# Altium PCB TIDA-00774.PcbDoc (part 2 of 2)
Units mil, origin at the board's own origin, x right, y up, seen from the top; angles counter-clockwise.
Board outline 2559.06 x 2362.2 mil, 4 copper layers (Top Layer, GND, PWR, Bottom Layer), stack 79.834 mil thick; 133 components, 91 nets, 569 pads, 616 vias.
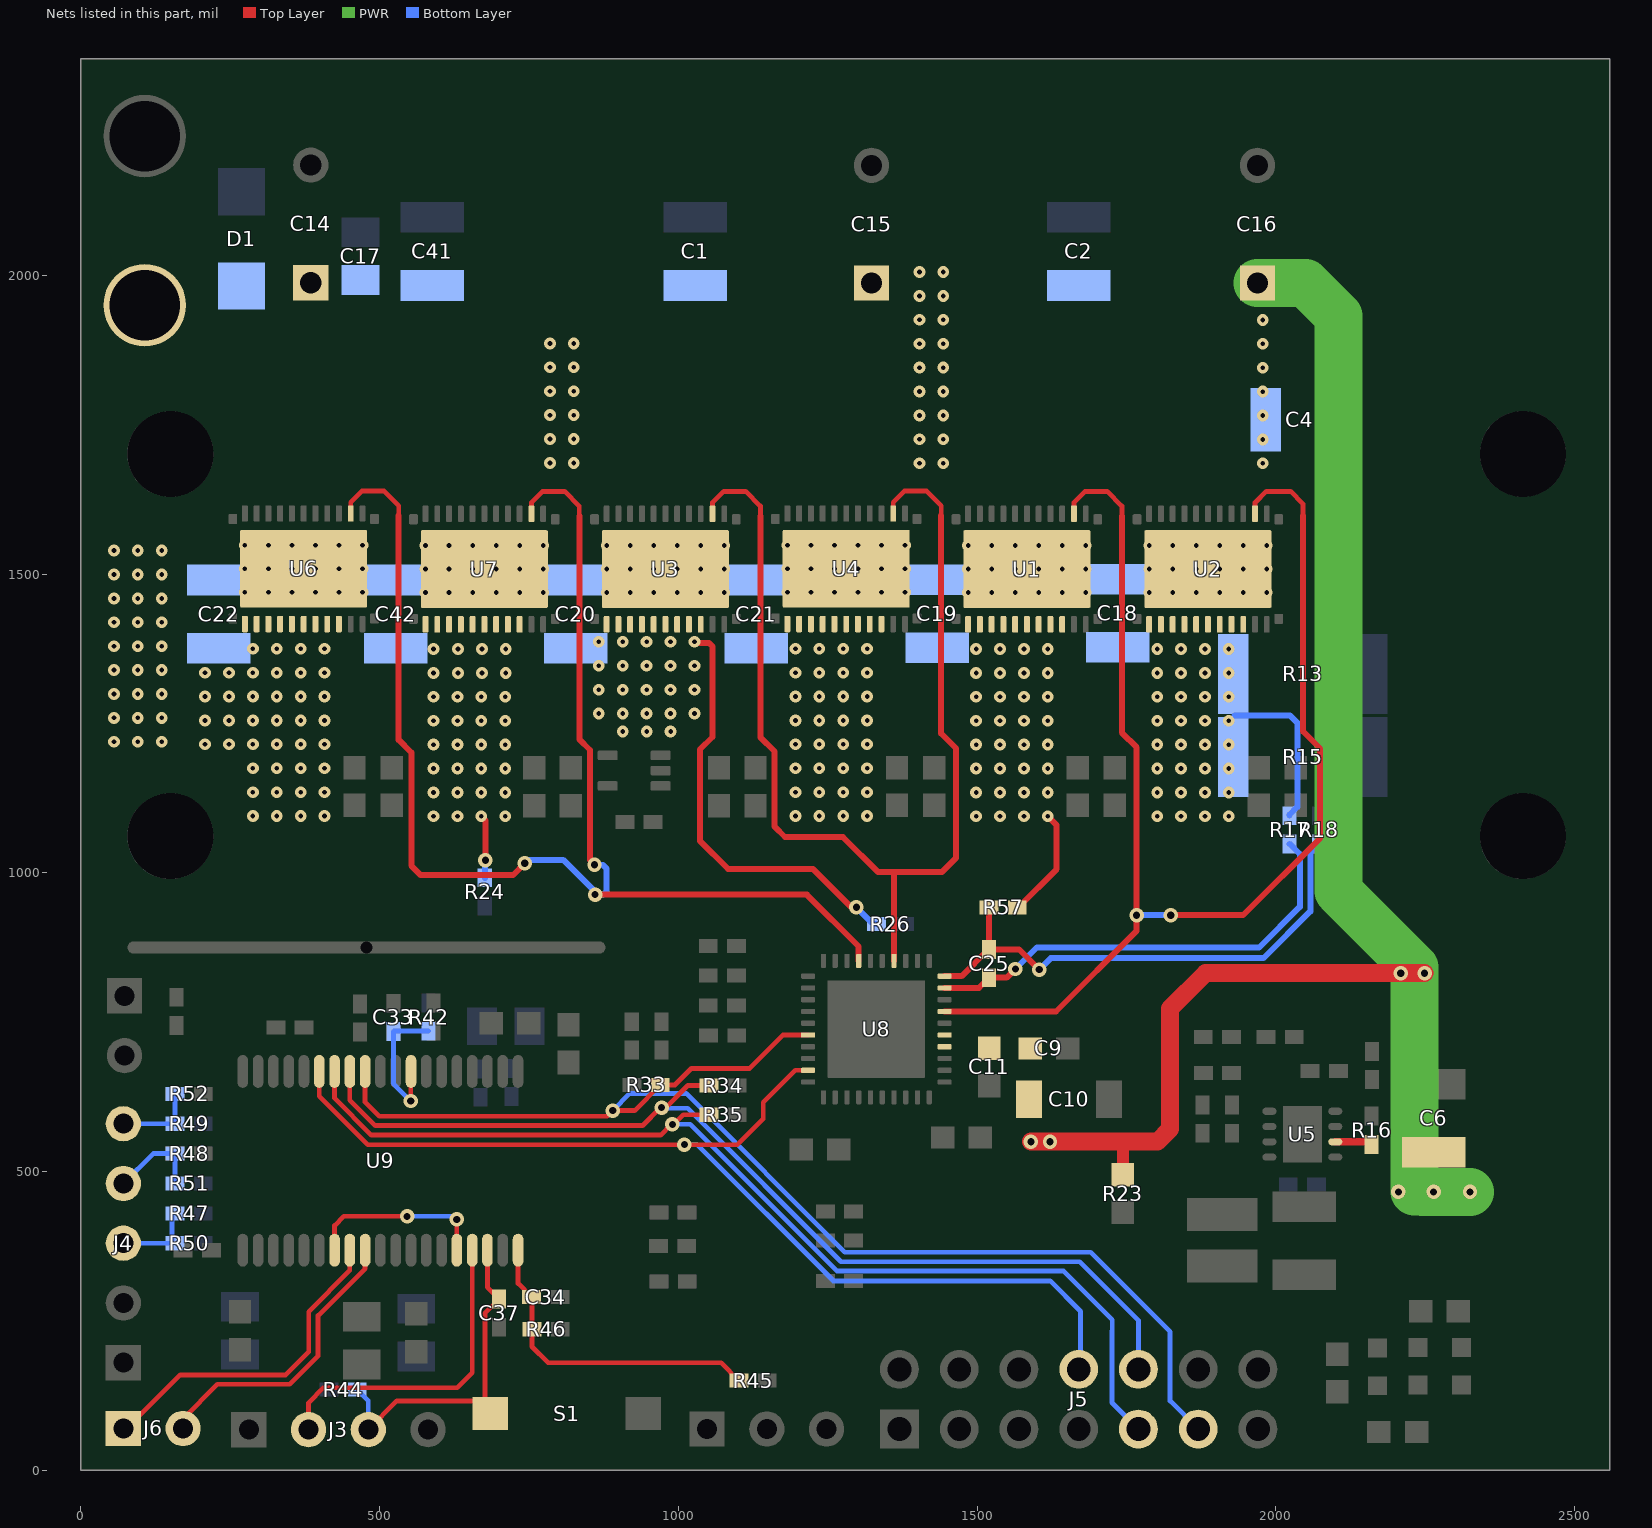
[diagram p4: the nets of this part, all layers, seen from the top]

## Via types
v1: diameter 19.68, hole 7.87, Top Layer to Bottom Layer, 491 vias
v2: diameter 24, hole 12, Top Layer to Bottom Layer, tented both sides, 125 vias

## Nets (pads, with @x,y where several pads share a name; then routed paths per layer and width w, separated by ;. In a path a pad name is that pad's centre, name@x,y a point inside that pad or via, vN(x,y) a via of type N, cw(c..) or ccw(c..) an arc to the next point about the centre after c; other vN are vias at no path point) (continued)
OC_FLT: U9.26 U9.34 | length 305.8
  Top Layer w8: U9.26@424.53,368.39 424.53,409.53 440,425 v2(546,425) ; v2(629,420) 629,368.65 U9.34@629.25,368.39
  Bottom Layer w8: v2(546,425) 624,425 v2(629,420)
PVDD: C1.1 C2.1 C4.1 C6.1 C9.1 C10.2 C11.1 C14.1 C15.1 C16.1 C17.1 C18.1 C19.1 C20.1 C21.1 C22.1 C41.1 C42.1 D1.2 pad.0 R16.2 R23.2 U1.27 U2.27 U3.27 U4.27 U5.2 U6.27 U7.27 U8.4 U8.5 | length 2771.1
  Top Layer w12: U5.2@2099.46,549.73 R16.2@2155.17,549.73
  Top Layer w15: R16.2@2155.17,549.73 R16.2@2161,543.91
  Top Layer w20: R23.2@1744,494.5 1744,549
  Top Layer w30: v2(1590,550) v2(1622,550) 1745,550 ; 1744,549 1745,550 ; v2(2249,832) v2(2209,832) 1882,832 1823,773 1823,571 1802,550 1745,550
  PWR w80: C16.1@1969.23,1987.18 2049.82,1987.18 2105,1932 2105,969 2232.17,841.83 2232.17,466.17 ; 2245,466 v2(2264,466) v2(2325,466)
  other v1: 55.3,1219.26 95.3,1219.26 135.3,1219.26 55.3,1259.26 95.3,1259.26 135.3,1259.26 55.3,1299.26 95.3,1299.26 135.3,1299.26 55.3,1339.26 95.3,1339.26 135.3,1339.26 55.3,1379.26 95.3,1379.26 135.3,1379.26 55.3,1419.26 95.3,1419.26 135.3,1419.26 55.3,1459.26 95.3,1459.26 135.3,1459.26 576.85,1469 616.22,1469 655.59,1469 694.96,1469 734.33,1469 773.7,1469 879.91,1469 919.28,1469 958.65,1469 998.02,1469 1037.39,1469 1076.76,1469 1484.91,1469 1524.28,1469 1563.65,1469 1603.02,1469 1642.39,1469 1681.76,1469 1787.91,1469 1827.28,1469 1866.65,1469 1906.02,1469 1945.39,1469 1984.76,1469 274.46,1469.48 313.83,1469.48 353.2,1469.48 392.57,1469.48 431.94,1469.48 471.31,1469.48 1182.46,1469.48 1221.83,1469.48 1261.2,1469.48 1300.57,1469.48 1339.94,1469.48 1379.31,1469.48 55.3,1499.26 95.3,1499.26 135.3,1499.26 274.46,1508.85 313.83,1508.85 353.2,1508.85 392.57,1508.85 431.94,1508.85 471.31,1508.85 576.85,1508.37 616.22,1508.37 655.59,1508.37 694.96,1508.37 734.33,1508.37 773.7,1508.37 879.91,1508.37 919.28,1508.37 958.65,1508.37 998.02,1508.37 1037.39,1508.37 1076.76,1508.37 1182.46,1508.85 1221.83,1508.85 1261.2,1508.85 1300.57,1508.85 1339.94,1508.85 1379.31,1508.85 1484.91,1508.37 1524.28,1508.37 1563.65,1508.37 1603.02,1508.37 1642.39,1508.37 1681.76,1508.37 1787.91,1508.37 1827.28,1508.37 1866.65,1508.37 1906.02,1508.37 1945.39,1508.37 1984.76,1508.37 55.3,1539.26 95.3,1539.26 135.3,1539.26 274.46,1548.22 313.83,1548.22 353.2,1548.22 392.57,1548.22 431.94,1548.22 471.31,1548.22 576.85,1547.74 616.22,1547.74 655.59,1547.74 694.96,1547.74 734.33,1547.74 773.7,1547.74 879.91,1547.74 919.28,1547.74 958.65,1547.74 998.02,1547.74 1037.39,1547.74 1076.76,1547.74 1182.46,1548.22 1221.83,1548.22 1261.2,1548.22 1300.57,1548.22 1339.94,1548.22 1379.31,1548.22 1484.91,1547.74 1524.28,1547.74 1563.65,1547.74 1603.02,1547.74 1642.39,1547.74 1681.76,1547.74 1787.91,1547.74 1827.28,1547.74 1866.65,1547.74 1906.02,1547.74 1945.39,1547.74 1984.76,1547.74 1978.23,1685.34 785,1686 825,1686 1403.45,1685.52 1443.45,1685.52 1978.23,1725.34 785,1726 825,1726 1403.45,1725.52 1443.45,1725.52 1978.23,1765.34 785,1766 825,1766 1403.45,1765.52 1443.45,1765.52 1978.23,1805.34 785,1806 825,1806 1403.45,1805.52 1443.45,1805.52 1978.23,1845.34 785,1846 825,1846 1403.45,1845.52 1443.45,1845.52 1978.23,1885.34 785,1886 825,1886 1403.45,1885.52 1443.45,1885.52 1978.23,1925.34 1403.45,1925.52 1443.45,1925.52 1403.45,1965.52 1443.45,1965.52 1403.45,2005.52 1443.45,2005.52
  other v2: 2205,466
RST: C37.1 J3.3 R44.1 S1.2 U9.36 | length 589.8
  Top Layer w8: J3.3@481,68 529,116 664.05,116 S1.2@676.21,103.84 ; U9.36@680.43,368.39 680.43,306.19 C37.1@700,286.62 676.21,262.83 S1.2@676.21,103.84 ; S1.2@685.05,95 S1.2@676.21,103.84
  Bottom Layer w8: R44.1@462.62,135 481,116.63 J3.3@481,68
SA: J4.5 R49.1 R52.2 | length 136.4
  Bottom Layer w8: J4.5@71,580 R49.1@157.38,580 R52.2@157.38,630
SB: J4.4 R48.1 R51.2 | length 157.1
  Bottom Layer w8: J4.4@71,480 121,530 R48.1@157.38,530 R51.2@157.38,480
SC: J4.3 R47.1 R50.2 | length 131.4
  Bottom Layer w8: J4.3@71,380 152.38,380 R47.1@152.38,430
SCLK: J5.9 R35.2 U9.13 | length 1793.1
  Top Layer w8: U9.13@424.53,667.61 424.53,622.78 486.19,561.12 970.12,561.12 988,579 v2(990,579) 990,576.8 1008.2,595 R35.2@1051.38,595
  Bottom Layer w8: v2@990,573.18 v2(990,579) 1019.93,579 1265.59,333.34 1278.68,333.34 ; 1278.74,333.4 1644.6,333.4 1726,252 1726,234 1725.72,233.72 1725.72,113.28 J5.9@1770,69
SCS: J5.8 U8.29 U9.14 | length 1838.5
  Top Layer w8: U9.14@398.94,667.61 398.94,626.03 480.17,544.8 480.37,545 v2(1010,545) 1098.6,545 1098.8,544.8 1142,588 1142,616.03 1195.46,669.5 U8.29@1217.16,669.5
  Bottom Layer w8: v2(1010,545) 1031.59,545 1259.59,317 1622,317 1673,266 1673,172 J5.8@1670,169
SDI: J5.10 R34.2 U9.12 | length 1736
  Top Layer w8: U9.12@450.12,667.61 450.12,619.54 492.74,576.92 939.92,576.92 970,607 v2(972,607) 972,602.13 973,601.13 1015.87,644 R34.2@1051.38,644
  Bottom Layer w8: v2(972,607) 970,607 969,606 1015.27,606 1272.14,349.14 1272.2,349.2 1671.8,349.2 1770,251 J5.10@1770,169
SDO: J5.11 R33.2 U8.26 U9.11 | length 2151.4
  Top Layer w8: U9.11@475.71,667.61 475.71,616.29 499.28,592.72 880.72,592.72 v2(890,602) 926.62,602 R33.2@969.62,645 994.34,645 1021.94,672.6 1119.26,672.6 1175.21,728.55 U8.26@1217.16,728.55
  Bottom Layer w8: v2(890,602) 918.8,630.8 1012.82,630.8 1278.62,365 1690,365 1823,232 1823,116 J5.11@1870,69
SH_A: U1.2 U2.2 U8.7 | length 2262.7
  Top Layer w8: U1.2@1662.04,1600.89 1662.04,1619.6 1680.76,1638.32 1717.85,1638.32 1742.3,1613.86 1742.3,1597.52 ; U2.2@1965.04,1600.89 1965.04,1619.6 1983.76,1638.32 2024.68,1638.32 2045.3,1617.7 2045.3,1598
  Top Layer w10: U8.7@1445.5,767.92 1631.92,767.92 1767,903 v2(1767,929) 1767,1210 1742.3,1234.7 1742.3,1597.52 ; v2(1824,929) 1945,929 2074,1058 2074,1208 2045.3,1236.7 2045.3,1598
  Bottom Layer w10: v2(1767,929) v2(1824,929)
SH_B: U3.2 U4.2 U8.14 | length 1874.3
  Top Layer w8: U3.2@1057.04,1600.89 1057.04,1619.6 1075.76,1638.32 1112.85,1638.32 1137.3,1613.86 1137.3,1597.52 ; U4.2@1359.59,1601.37 1359.59,1620.08 1378.31,1638.8 1415.39,1638.8 1439.85,1614.34 1439.85,1598
  Top Layer w10: 1137.3,1597.52 1137.3,1226.7 1161,1203 1161,1077.25 1178.37,1059.88 1275.39,1059.88 1334.27,1001 1362,1001 ; U8.14@1360.86,852.57 1360.86,999.86 1362,1001 ; 1439.85,1598 1439.85,1233.15 1465,1208 1465,1025 1441,1001 1362,1001
SH_C: U6.2 U7.2 U8.17 | length 2386.5
  Top Layer w8: U6.2@451.59,1601.37 451.59,1620.08 470.31,1638.8 507.39,1638.8 531.85,1614.34 531.85,1598 ; U7.2@753.98,1600.89 753.98,1619.6 772.7,1638.32 809.79,1638.32 834.24,1613.86 834.24,1597.52
  Top Layer w10: 531.85,1598 531.85,1222.42 553,1201.27 553,1012 568.8,996.2 723.2,996.2 v2(743,1016) ; 834.24,1597.52 834.24,1223.26 852,1205.5 852,1021.15 v2(859.68,1013.48) ; v2(860.68,963.48) 1214.96,963.48 1301.8,876.64 U8.17@1301.8,852.57
  Bottom Layer w10: v2(743,1016) 748.8,1021.8 807.2,1021.8 v2@860.68,968.32 ; v2(859.68,1013.48) 873.52,1013.48 880,1007 880,969 874.48,963.48 v2(860.68,963.48)
SL_A: C18.2 C19.2 C20.2 C21.2 C22.2 C42.2 R13.1 R15.1 R17.2 R24.1 R26.1 R57.1 U1.12 U1.13 U1.14 U1.15 U1.16 U1.17 U1.18 U1.19 U1.20 U2.12 U2.13 U2.14 U2.15 U2.16 U2.17 U2.18 U2.19 U2.20 U3.12 U3.13 U3.14 U3.15 U3.16 U3.17 U3.18 U3.19 U3.20 U4.12 U4.13 U4.14 U4.15 U4.16 U4.17 U4.18 U4.19 U4.20 U6.12 U6.13 U6.14 U6.15 U6.16 U6.17 U6.18 U6.19 U6.20 U7.12 U7.13 U7.14 U7.15 U7.16 U7.17 U7.18 U7.19 U7.20 | length 1290.8
  Top Layer w10: v1(670.24,1094.52) 677,1087.76 v2(677,1021) ; v1@1026.8,1385 1051,1385 1057,1379 1057,1227.33 1036,1206.33 1036,1053.48 1083,1006.48 1225.14,1006.48 1289.24,942.37 v2(1297.9,942.37) ; R57.1@1567.24,942 1569,942 1633,1006 1633,1079.82 v1(1618.3,1094.52)
  Bottom Layer w10: R24.1@676,991.62 676,1020 v2(677,1021) v2@677,1028 ; v2(1297.9,942.37) 1326.27,914 R26.1@1331.38,914 ; 1931,1263 2024,1263 2036,1251 2036,1110.49 2023,1097.49 R17.2@2023,1095.62
  other v1: 287.85,1095 327.85,1095 367.85,1095 407.85,1095 590.24,1094.52 630.24,1094.52 710.24,1094.52 1195.85,1095 1235.85,1095 1275.85,1095 1315.85,1095 1498.3,1094.52 1538.3,1094.52 1578.3,1094.52 1801.3,1094.52 1841.3,1094.52 1881.3,1094.52 1921.3,1094.52 287.85,1135 327.85,1135 367.85,1135 407.85,1135 590.24,1134.52 630.24,1134.52 670.24,1134.52 710.24,1134.52 1195.85,1135 1235.85,1135 1275.85,1135 1315.85,1135 1498.3,1134.52 1538.3,1134.52 1578.3,1134.52 1618.3,1134.52 1801.3,1134.52 1841.3,1134.52 1881.3,1134.52 1921.3,1134.52 287.85,1175 327.85,1175 367.85,1175 407.85,1175 590.24,1174.52 630.24,1174.52 670.24,1174.52 710.24,1174.52 1195.85,1175 1235.85,1175 1275.85,1175 1315.85,1175 1498.3,1174.52 1538.3,1174.52 1578.3,1174.52 1618.3,1174.52 1801.3,1174.52 1841.3,1174.52 1881.3,1174.52 1921.3,1174.52 207.85,1215 247.85,1215 287.85,1215 327.85,1215 367.85,1215 407.85,1215 590.24,1214.52 630.24,1214.52 670.24,1214.52 710.24,1214.52 1195.85,1215 1235.85,1215 1275.85,1215 1315.85,1215 1498.3,1214.52 1538.3,1214.52 1578.3,1214.52 1618.3,1214.52 1801.3,1214.52 1841.3,1214.52 1881.3,1214.52 1921.3,1214.52 907,1236.5 947,1236.5 987,1236.5 207.85,1255 247.85,1255 287.85,1255 327.85,1255 367.85,1255 407.85,1255 590.24,1254.52 630.24,1254.52 670.24,1254.52 710.24,1254.52 1195.85,1255 1235.85,1255 1275.85,1255 1315.85,1255 1498.3,1254.52 1538.3,1254.52 1578.3,1254.52 1618.3,1254.52 1801.3,1254.52 1841.3,1254.52 1881.3,1254.52 1921.3,1254.52 866.8,1266.52 906.8,1266.52 946.8,1266.52 986.8,1266.52 1026.8,1266.52 207.85,1295 247.85,1295 287.85,1295 327.85,1295 367.85,1295 407.85,1295 590.24,1294.52 630.24,1294.52 670.24,1294.52 710.24,1294.52 1195.85,1295 1235.85,1295 1275.85,1295 1315.85,1295 1498.3,1294.52 1538.3,1294.52 1578.3,1294.52 1618.3,1294.52 1801.3,1294.52 1841.3,1294.52 1881.3,1294.52 1921.3,1294.52 866.8,1306.52 906.8,1306.52 946.8,1306.52 986.8,1306.52 1026.8,1306.52 207.85,1335 247.85,1335 287.85,1335 327.85,1335 367.85,1335 407.85,1335 590.24,1334.52 631.24,1334.52 671.24,1334.52 711.24,1334.52 1195.85,1335 1235.85,1335 1275.85,1335 1315.85,1335 1498.3,1334.52 1538.3,1334.52 1578.3,1334.52 1618.3,1334.52 1801.3,1334.52 1841.3,1334.52 1881.3,1334.52 1921.3,1334.52 866.8,1346.52 906.8,1346.52 946.8,1346.52 986.8,1346.52 1026.8,1346.52 287.85,1375 327.85,1375 367.85,1375 407.85,1375 590.24,1374.52 631.24,1374.52 671.24,1374.52 711.24,1374.52 1195.85,1375 1235.85,1375 1275.85,1375 1315.85,1375 1498.3,1374.52 1538.3,1374.52 1578.3,1374.52 1618.3,1374.52 1801.3,1374.52 1841.3,1374.52 1881.3,1374.52 1921.3,1374.52 866.8,1386.52 906.8,1386.52 946.8,1386.52 986.8,1386.52 1026.8,1386.52
SN1: C25.2 R18.1 R57.2 U8.10 | length 874.2
  Top Layer w10: U8.10@1445.5,826.98 1473.98,826.98 1518.62,871.62 C25.2@1520,871.62 ; R57.2@1520,942 C25.2@1520,871.62 ; v2(1604,838) 1570.38,871.62 C25.2@1520,871.62
  Bottom Layer w10: v2(1604,838) 1623.2,857.2 1979.37,857.2 2057.8,935.63 2057.8,1034.18 R18.1@2072,1048.38
SP1: C25.1 R17.1 U8.9 | length 763.1
  Top Layer w10: U8.9@1445.5,807.29 1502.92,807.29 C25.1@1520,824.38 1549.38,824.38 v2(1564,839)
  Bottom Layer w10: v2(1564,839) 1600,875 1972,875 2040,943 2040,1031.38 R17.1@2023,1048.38
SPEED_REF: C34.1 R45.1 R46.2 U9.38 | length 541.1
  Top Layer w8: U9.38@731.61,368.39 731.61,312.76 C34.1@754.38,290 755,289.38 R46.2@755,236 755,207 782,180 1071.38,180 R45.1@1101.38,150
TEMP_SENSE: C33.1 R42.1 U9.8 | length 239.1
  Top Layer w8: v2(552,618) 552,663.13 550,665.13 U9.8@552.48,667.61
  Bottom Layer w8: v2(552,618) 523,647 C33.1@523,734.38 523.62,735 R42.1@582,735
TEST: J3.2 U9.35 | length 544.8
  Top Layer w8: J3.2@381,68 381,113 406,138 629.66,138 654.84,163.18 U9.35@654.84,368.39
UART_RX: J6.2 U9.28 | length 495.5
  Top Layer w8: J6.2@171,70 171,86.44 228.39,143.83 349.38,143.83 397,191.46 397,258.95 475.71,337.66 U9.28@475.71,368.39
UART_TX: J6.1 U9.27 | length 562.2
  Top Layer w8: J6.1@71,70 77,70 166.63,159.63 342.83,159.63 381.2,198 381.2,265.5 450.12,334.42 U9.27@450.12,368.39
pads on no net: U1. U1.21 U1.23 U1.24 U1.25 U1.26 U2. U2.21 U2.23 U2.24 U2.25 U2.26 U3. U3.21 U3.23 U3.24 U3.25 U3.26 U4. U4.21 U4.23 U4.24 U4.25 U4.26 U6. U6.21 U6.23 U6.24 U6.25 U6.26 U7. U7.21 U7.23 U7.24 U7.25 U7.26 U8.12 U8.19 U8.41@1277.39,684.46 U8.41@1277.39,738.4 U8.41@1277.39,792.33 U8.41@1331.33,684.46 U8.41@1331.33,738.4 U8.41@1331.33,792.33 U8.41@1385.27,684.46 U8.41@1385.27,738.4 U8.41@1385.27,792.33

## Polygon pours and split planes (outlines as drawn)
NetC27_1 on Bottom Layer "Bottom Layer-No Net 1" (solid, remove dead copper, pour order 220): 842,805 734,805 726,797 726,726 730,722 836.54,722 844.54,730 844.54,802.46
GND on Bottom Layer "Bottom Layer-No Net 1" (solid, remove dead copper, pour order 230): 2525,439.02 2525,50 2508,33 55,33 34,54 34,1005 53,1024 59,1030 1027,1030 2108,1030 2117,1030 2126,1039 2126,1115 2133,1122 2286,1122 2294,1114 2294,910 2303,901 2518,901 2525,894
GND on Bottom Layer "Bottom Layer-No Net 1" (solid, remove dead copper, pour order 338): 59,2053 2012,2053 2043,2022 2043,1453 2053,1443 2118,1443 2126,1435 2126,1294 2126,1104 2167,1063 2478,1063 2529,1114 2529,2305 2504,2330 61,2330 41,2310 41,2071
PVDD on Bottom Layer "Bottom Layer-No Net 1" (solid, remove dead copper, pour order 354): 60,2019 2000,2019 2010,2009 2010,1456 1995,1441 157,1441 150,1434 150,1431 150,1200 146,1196 138,1196 44,1196 41,1199 41,2000
SL_A on Bottom Layer "Bottom Layer-No Net 1" (solid, remove dead copper, pour order 360): 187,1421 178,1412 178,1198 180,1196 182,1196 265,1196 269.5,1191.5 269.5,1075.5 284,1061 1949,1061 1958,1070 1958,1410 1947,1421
GND on Top Layer "Bottom Layer-No Net 1" (solid, remove dead copper, pour order 128): 600.95,218 426,218 414.32,206.32 414.32,129.63 422.32,121.63 588.63,121.63 606.32,139.32 606.32,212.63
PVDD on Top Layer "Bottom Layer-No Net 1" (solid, remove dead copper, pour order 134): 1615,735 1436,735 1433,732 1433,705 1436,702 1481,702 1500,683 1558.74,683 1573.48,668.26 1573.48,541.52 1580,535 1637,535 1639,537 1639,728 1632,735
GND on Top Layer "Bottom Layer-No Net 1" (solid, remove dead copper, pour order 136): 1656,725 1656,591 1666,581 1780,581 1785,586 1785,725 1782,728 1659,728
GND on Top Layer "Bottom Layer-No Net 1" (solid, remove dead copper, pour order 212): 2043,2322 2043,1475 2075,1443 2118,1443 2126,1435 2126,1002 2142,986 2502,986 2527,1011 2527,2307 2505.05,2328.95 2049.95,2328.95
NetC3_1 on Top Layer "Bottom Layer-No Net 1" (solid, remove dead copper, pour order 188): 1851,530 1844,523 1844,399.98 1846.31,397.67 1973.69,397.67 1973.69,499.75 1976.43,502.49 1995.49,502.49 2000,507 2000,528 1998,530
GND on Top Layer "Bottom Layer-No Net 1" (solid, remove dead copper, pour order 206): 2104,413 1996,413 1991,418 1991,473.44 1993,475.44 2008.89,475.44 2012,478.55 2014.13,480.68 2014.13,698.5 2014.13,778.44 2021,785.31 2321,785.31 2331,775.31 2331,615.31 2324,608.31 2206,608.31 2199,615.31 2199,690.31 2195,694.31 2080.31,694.31 2075,689 2073.87,687.87 2073.87,641.29 2073.87,480.88 2078,476.76 2098.24,476.76 2108,467 2108,417
3.3V on Top Layer "Bottom Layer-No Net 1" (solid, remove dead copper, pour order 210): 1973.69,372.33 1846.31,372.33 1846.31,256.69 1855,248 2184,248 2191,255 2191,359 2178,372
PVDD on Top Layer "Bottom Layer-No Net 1" (solid, remove dead copper, pour order 214): 2148.3,569.13 2342.87,569.13 2345,567 2345,445 2339,439 2181,439 2177,443 2177,507 2168,516 2142.38,516 2138.46,519.91 2138.46,559.28 2148.3,569.13
NetC27_1 on Top Layer "Bottom Layer-No Net 1" (solid, remove dead copper, pour order 216): 832,805 743,805 726,788 726,726 730,722 836.54,722 844.54,730 844.54,792.46
GND on Top Layer "Bottom Layer-No Net 1" (solid, remove dead copper, pour order 232): 171.05,899.05 34,762 34,47 48,33 2508,33 2525,50 2525,894 2518.74,900.26
SL_A on Top Layer "Bottom Layer-No Net 1" (solid, remove dead copper, pour order 246): 737.09,1429.56 575.09,1429.56 572.09,1426.56 572.09,1088.85 581.94,1079 716,1079 725,1088 725,1226.32 730.23,1231.56 740.09,1241.41 740.09,1388.56 740.09,1426.56
SL_A on Top Layer "Bottom Layer-No Net 1" (solid, remove dead copper, pour order 248): 1040.15,1429.56 878.15,1429.56 875.15,1426.56 875.14,1402 860.12,1402 854.62,1396.5 854.62,1232.38 875.15,1211.85 875.15,1088.85 885,1079 1004,1079 1015.3,1090.3 1015.3,1213.56 1033.3,1231.56 1043.15,1241.41 1043.15,1388.56 1043.15,1426.56
SL_A on Top Layer "Bottom Layer-No Net 1" (solid, remove dead copper, pour order 250): 1342.7,1430.04 1180.7,1430.04 1177.7,1427.04 1177.7,1089.33 1187.55,1079.48 1321.48,1079.48 1329.5,1087.5 1329.5,1225.7 1335.84,1232.04 1345.7,1241.89 1345.7,1389.04 1345.7,1427.04
SL_A on Top Layer "Bottom Layer-No Net 1" (solid, remove dead copper, pour order 252): 1645.15,1429.56 1483.15,1429.56 1480.15,1426.56 1480.15,1088.85 1490,1079 1621.5,1079 1631.5,1089 1631.5,1224.76 1638.3,1231.56 1648.15,1241.41 1648.15,1388.56 1648.15,1426.56
SL_A on Top Layer "Bottom Layer-No Net 1" (solid, remove dead copper, pour order 260): 1948.15,1429.56 1786.15,1429.56 1783.15,1426.56 1783.15,1088.85 1793,1079 1925.5,1079 1934.5,1088 1934.5,1224.76 1941.3,1231.56 1951.15,1241.41 1951.15,1388.56 1951.15,1426.56
SL_A on Top Layer "Top Layer-MU" (solid, remove dead copper, pour order 372): 269.7,1427.04 269.7,1380.7 266,1377 186,1377 178,1369 178,1198 180,1196 265,1196 269.5,1191.5 269.5,1089.53 279.55,1079.48 412.98,1079.48 422,1088.5 422,1226.2 437.7,1241.89 437.7,1426.28 433.94,1430.04 273.45,1430.04 269.7,1426.28
MW on Top Layer "Top Layer-MU" (solid, remove dead copper, pour order 374): 269.5,1588.5 269.5,1922.5 277,1930 419,1930 436,1947 436,2309 457,2330 803,2330 817,2316 817,1959 740,1882 740,1700.91 740,1593.65 733.98,1587.63 574.83,1587.63 571.89,1590.57 571.89,1653.11 566,1659 443,1659 432,1648 432,1589 429,1586 272,1586
MV on Top Layer "Top Layer-MU" (solid, remove dead copper, pour order 376): 874.95,1588.02 874.95,2291.35 874.95,2319 884.95,2329 1254,2329 1267,2316 1267,1940 1285,1922 1345.45,1861.55 1345.45,1820.85 1345.45,1592.38 1340.23,1587.15 1180.29,1587.15 1177.5,1589.94 1177.5,1652.47 1171.45,1658.52 1048.45,1658.52 1037.45,1647.52 1037.45,1584.52 878.45,1584.52 874.95,1588.02 875.97,1587
MU on Top Layer "Top Layer-MU" (solid, remove dead copper, pour order 378): 1479.95,1588.02 1479.95,2021.05 1383,2118 1383,2317 1395,2329 1900,2329 1913,2316 1913,1899 1950.45,1861.55 1950.45,1820.85 1950.45,1592.38 1945.23,1587.15 1785.29,1587.15 1782.5,1589.94 1782.5,1652.47 1776.45,1658.52 1653.45,1658.52 1642.45,1647.52 1642.45,1584.52 1483.45,1584.52 1479.95,1588.02 1480.97,1587
GND on GND "Bottom Layer-No Net 1" (solid, remove dead copper, pour order 138): 171.05,899.05 34,762 34,47 48,33 2508,33 2525,50 2525,894 2518.74,900.26
GND on GND "Bottom Layer-No Net 1" (solid, remove dead copper, pour order 186): 59,2053 2012,2053 2043,2022 2043,1453 2053,1443 2118,1443 2126,1435 2126,1294 2126,1002 2142,986 2401,986 2529,1114 2529,2305 2504,2330 61,2330 41,2310 41,2071
PVDD on GND "Bottom Layer-No Net 1" (solid, remove dead copper, pour order 342): 60,2019 2000,2019 2010,2009 2010,1456 1995,1441 157,1441 150,1434 150,1431 150,1200 146,1196 138,1196 44,1196 41,1199 41,2000
SL_A on GND "Bottom Layer-No Net 1" (solid, remove dead copper, pour order 362): 187,1421 178,1412 178,1198 180,1196 182,1196 265,1196 269.5,1191.5 269.5,1075.5 284,1061 1949,1061 1958,1070 1958,1410 1947,1421
NetC27_1 on PWR "Bottom Layer-No Net 1" (solid, remove dead copper, pour order 140): 190,282 190,241 194.24,236.76 601.76,236.76 810.2,445.2 810.2,802.56 806,806.76 753,806.76 750,803.76 750,467 569.76,286.76 194.76,286.76
3.3V on PWR "Bottom Layer-No Net 1" (solid, remove dead copper, pour order 228): 171.05,899.05 34,762 34,47 48,33 2508,33 2525,50 2525,894 2518.74,900.26
PVDD on PWR "Bottom Layer-No Net 1" (solid, remove dead copper, pour order 356): 60,2019 2000,2019 2010,2009 2010,1456 1995,1441 157,1441 150,1434 150,1431 150,1200 146,1196 138,1196 44,1196 41,1199 41,2000
SL_A on PWR "Bottom Layer-No Net 1" (solid, remove dead copper, pour order 364): 187,1421 178,1412 178,1198 180,1196 182,1196 265,1196 269.5,1191.5 269.5,1075.5 284,1061 1949,1061 1958,1070 1958,1410 1947,1421
no net on M3 3D STEP Top "Bottom Layer-No Net 1" (solid, remove dead copper, pour order 218): 2518,436.02 2518,47 2501,30 48,30 27,51 27,1002 46,1021 52,1027 1020,1027 2101,1027 2110,1027 2119,1036 2119,1112 2126,1119 2279,1119 2287,1111 2287,907 2296,898 2511,898 2518,891
SL_A on Top Solder "Bottom Layer-No Net 1" (solid, pour order 236): 1342.7,1430.04 1180.7,1430.04 1177.7,1427.04 1177.7,1089.33 1187.55,1079.48 1321.48,1079.48 1330,1088 1330,1226.2 1335.84,1232.04 1345.7,1241.89 1345.7,1389.04 1345.7,1427.04
SL_A on Top Solder "Bottom Layer-No Net 1" (solid, pour order 238): 1040.15,1429.56 878.15,1429.56 875.15,1426.56 875.03,1409.53 875.15,1402 860.12,1402 854.63,1396.51 854.63,1235.89 866.53,1224 1025.74,1224 1043.15,1241.41 1043.15,1388.56 1043.15,1426.56
SL_A on Top Solder "Bottom Layer-No Net 1" (solid, pour order 234): 1645.15,1429.56 1483.15,1429.56 1480.15,1426.56 1480.15,1088.85 1490,1079 1621.5,1079 1631.5,1089 1631.5,1224.76 1638.3,1231.56 1648.15,1241.41 1648.15,1388.56 1648.15,1426.56
SL_A on Top Solder "Bottom Layer-No Net 1" (solid, pour order 240): 737.09,1429.56 575.09,1429.56 572.09,1426.56 572.09,1088.85 581.94,1079 716,1079 725,1088 725,1226.32 730.23,1231.56 740.09,1241.41 740.09,1388.56 740.09,1426.56
SL_A on Top Solder "Bottom Layer-No Net 1" (solid, pour order 124): 1948.15,1429.56 1786.15,1429.56 1783.15,1426.56 1783.15,1088.85 1793,1079 1925.5,1079 1934.5,1088 1934.5,1224.76 1941.3,1231.56 1951.15,1241.41 1951.15,1388.56 1951.15,1426.56
SL_A on Top Solder "Top Layer-MU" (solid, pour order 370): 269.7,1427.04 269.7,1380.7 266,1377 186,1377 178,1369 178,1198 180,1196 265,1196 269.5,1191.5 269.5,1089.53 279.55,1079.48 412.98,1079.48 422,1088.5 422,1226.2 437.7,1241.89 437.7,1426.28 433.94,1430.04 273.45,1430.04 269.7,1426.28
MW on Top Solder "Top Layer-MU" (solid): 272,1586 269.5,1588.5 269.5,1874.5 280.5,1885.5 510.5,1885.5 601,1976 601,2313 605,2317 812,2317 817,2312 817,1959 740,1882 740,1593.65 733.98,1587.63 574.83,1587.63 571.89,1590.57 571.89,1653.11 566,1659 443,1659 432,1648 432,1589 429,1586
MV on Top Solder "Top Layer-MU" (solid): 878.45,1584.52 874.95,1588.02 874.95,2311.95 880,2317 1097,2317 1103,2311 1103,2000 1228,1875 1332,1875 1345.45,1861.55 1345.45,1592.38 1340.23,1587.15 1180.29,1587.15 1177.5,1589.94 1177.5,1652.47 1171.45,1658.52 1048.45,1658.52 1037.45,1647.52 1037.45,1584.52
MU on Top Solder "Top Layer-MU" (solid): 1483.45,1584.52 1479.95,1588.02 1479.95,1945.95 1514,1980 1541,2007 1541,2308 1541,2312 1546,2317 1747,2317 1754,2310 1754,1992 1870,1876 1936,1876 1950.45,1861.55 1950.45,1592.38 1945.23,1587.15 1785.29,1587.15 1782.95,1589.48 1782.95,1652.02 1776.45,1658.52 1653.45,1658.52 1642.45,1647.52 1642.45,1584.52
GND on Bottom Solder "Bottom Layer-No Net 1" (solid): 41,2310 41,2071 59,2053 2012,2053 2043,2022 2043,1453 2053,1443 2118,1443 2126,1435 2126,1127 2139,1114 2264,1114 2278,1128 2278,1178 2292,1192 2521,1192 2529,1200 2529,1547 2493,1583 2297,1583 2285,1595 2285,1785 2314,1814 2510,1814 2529,1833 2529,2305 2504,2330 61,2330 51,2320
SL_A on Bottom Solder "Bottom Layer-No Net 1" (solid, pour order 368): 187,1421 178,1412 178,1198 180,1196 182,1196 265,1196 269.5,1191.5 269.5,1075.5 284,1061 1949,1061 1958,1070 1958,1410 1947,1421
PVDD on Bottom Solder "Bottom Layer-No Net 1" (solid, pour order 366): 60,2019 2000,2019 2010,2009 2010,1456 1995,1441 157,1441 150,1434 150,1431 150,1200 146,1196 138,1196 44,1196 41,1199 41,1568.5 240.5,1568.5 285.5,1568.5 285.5,1755.5 285.5,1829.5 157,1829.5 44,1829.5 41,2000

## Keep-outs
Keep-Out Layer:
  circle w1: c150.28,1060.39 r118
  circle w1: c149.64,1700.91 r118
  circle w1: c2411.4,1703 r110.24
  circle w1: c2414.83,1060.39 r110.24
  lines w6: 20,20 2539.06,20 2539.06,2342.2 20,2342.2 20,20
  text ".Layer_Name" at -885.15,-1620.64 h60

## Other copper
Top Layer:
  text ".layer_Name" at -870.15,-1610.15 h60
GND:
  text "GND" at -850.15,-1620.15 h60
PWR:
  text "PWR" at -812.15,-1627.15 h60
Bottom Layer:
  pour cut-out: 895,884 103,884 34,815 34,1023 57,1046 1029,1046 1032,1043 1032,992 936,896
  pour cut-out: 985.44,1025 985.44,967.44 871,853 38.56,853 34,848.44 34,1004 69,1039 971.44,1039
  text ".Layer_Name" at -811.15,-1620.15 h60

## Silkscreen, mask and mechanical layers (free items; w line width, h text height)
Top Overlay:
  circle w10: c1014,1145 r5.83
  circle w10: c1985.76,1638.52 r7.99
  circle w10: c1682.76,1638.52 r7.99
  circle w10: c1380.31,1639 r7.99
  circle w10: c1077.76,1638.52 r7.99
  circle w10: c774.7,1638.52 r7.99
  circle w10: c472.31,1639 r7.99
  rectangle: 257,4 303,16
  rectangle: 42,8 88,20
  lines w6: 221,120 216,125 215,125 226,136 226,137 ; 307,125 307,128 313,134 ; 364,143 364,135 371,128 ; 404,140 404,136 409,131 469,131 473,127 ; 994.07,1127.83 1018,1103.91 1018,1066 ; 1307,134 1307,132 1320,119 ; 1849,380 1849,394 ; 1972,378 1972,392 ; 2269.5,99.24 2291.75,77
  lines w10: 2,906.69 2561.06,906.69 2561.06,1851.57 2,1851.57 2,906.69
  text "PHASE_C" at 608,2327 h30
  text "PHASE_B" at 897,2327 h30
  text "PHASE_A" at 1552,2327 h30
  text "GND" at 62,2314 h30
  text "+18VDC" at 10,2028 h30
  text "HA" at 131,565 h30
  text "HB" at 131,463 h30
  text "HC" at 131,398 h30
  text "GND" at 130,270 h30
  text "3.3V" at 128,189 h30
  text "RESET" at 832,181 h30
  text "RST" at 416,149 h30 r90
  text "3.3V" at 1065,146 h30 r90
  text "3.3V" at 335,142 h30 r90
  text "1" at 1296,142 h30
  text "TEST" at 377,141 h30 r90
  text "RX" at 211,132 h30 r90
  text "POT" at 1215,131 h30 r90
  text "GND" at 1265,131 h30 r90
  text "GND" at 633,130 h30 r90
  text "TX" at 166,127 h30 r90
  text "(FAULT)" at 2366,43 h30
  text ".layer_Name" at -844.15,-1608.15 h60
Bottom Overlay:
  lines w6: 1510,878 1510,1039 ; 1968,959 1968,738 2099,738 2099,967 ; 2038,977 2038,1003 2029,994 2048,994 2039,1003 ; 1510,1039 1502,1031 1519,1031 1511,1039 1510,1039 ; 978,486 1152,486 1848,486 1860,486 1860,874 978,874 978,486
  text ".Layer_Name" at -885.15,-1620.64 h60
Top Paste:
  text ".Layer_Name" at -897.15,-1623.64 h60
Bottom Paste:
  text ".Layer_Name" at -897.15,-1623.64 h60
Top Solder:
  text ".Layer_Name" at -869.15,-1631.15 h60
Bottom Solder:
  text ".Layer_Name" at -822.15,-1627.15 h60
M1 Board Outline:
  the board outline again, w6
  text "M1 Board Outline" at -864,-1616 h60
M2 Board Dimensions:
  rectangle: -867.65,-767.15 -492.65,-642.15
  rectangle: -992.65,-642.15 -867.65,-517.15
  lines w7: -992.65,-642.15 7.35,-642.15 ; -867.65,-767.15 -867.65,-517.15 ; -742.65,-767.15 -742.65,-517.15 ; -492.65,-767.15 -492.65,-517.15 ; -242.65,-767.15 -242.65,-517.15 ; -992.65,-767.15 -992.65,-517.15 7.35,-517.15 7.35,-767.15 -992.65,-767.15
  lines w10: -992.65,-832.15 -992.65,-812.15 ; -932.65,-842.15 -992.65,-822.15 ; -932.65,-802.15 -992.65,-822.15 ; -768.57,-822.15 -992.65,-822.15 ; -216.73,-822.15 7.35,-822.15 ; -52.65,-842.15 7.35,-822.15 ; -52.65,-802.15 7.35,-822.15 ; 7.35,-832.15 7.35,-812.15
  text "1000 (mil)" at -758.57,-858.14 h60
M3 3D STEP Top:
  text ".Layer_Name" at -885.15,-1620.64 h60
M4 3D STEP Bottom:
  text ".Layer_Name" at -885.15,-1620.64 h60
M5 Assembly Top:
  circle w10: c1001,1145 r7.62
  circle w10: c70,181 r19.24
  circle w10: c70,66 r19.24
  circle w10: c280,66 r19.24
  circle w10: c70,792 r19.24
  circle w10: c1046,66 r19.24
  lines w10: -1754.15,-1692.32 4845.85,-1692.32 ; -1754.15,-1488.98 4847.85,-1488.98 ; -1754.15,-1285.65 -1754.15,-1895.65 2250.85,-1895.65 4847.85,-1895.65 4847.85,-1285.65 -1753.65,-1285.65 -1753.65,-1895.65 ; 710.85,-1895.65 710.85,-1285.65 ; 1977.85,-1488.98 1977.85,-1285.65 ; 2817.85,-1488.98 2817.85,-1285.65 ; 3439.85,-1902.15 3439.85,-1699.32
  text "COMPONENTS MARKED 'DNP' SHOULD NOT BE POPULATED." at -308.65,-1080.65 h25
  text "ASSEMBLY VARIANT:" at -309.15,-1196.15 h25
  text ".VariantName" at 726.85,-1196.15 h25
  text "ALL ARTWORK VIEWED FROM TOP SIDE" at -1690.65,-1417.82 h25
  text "BOARD #:" at 785.85,-1417.82 h25
  text ".PRJ_Number" at 1331.35,-1417.82 h25
  text "REV:" at 2175.85,-1417.82 h25
  text ".PCB_Rev" at 2467.35,-1417.82 h25
  text "SVN REV:" at 3013.85,-1417.82 h25
  text ".VersionControl_RevNumber" at 3519.85,-1417.82 h25
  text ".layer_Name" at -927.15,-1600.15 h25
  text "LAYER NAME =" at -1697.15,-1607.15 h25
  text ".TID" at 1181,-1617 h25
  text "TID #:" at 774.85,-1623.82 h25
  text ".plot_File_Name" at -1699.15,-1796.15 h25
  text "GENERATED    :" at 787.85,-1826.49 h25
  text ".Print_Date" at 1657.35,-1826.49 h25
  text ".Print_Time" at 2386.35,-1826.49 h25
  text "TEXAS INSTRUMENTS" at 3650.85,-1826.49 h25
M6 Assembly Bottom:
  lines w6: -1754.65,-1489.48 4847.35,-1489.48 ; -1752.65,-1692.82 4847.35,-1692.82 ; 275.35,-1489.48 275.35,-1286.15 ; 1115.35,-1489.48 1115.35,-1286.15 ; 2382.35,-1896.15 2382.35,-1286.15 ; 3271.35,-1896.15 4846.85,-1896.15 4846.85,-1286.15 -1754.65,-1286.15 -1754.65,-1896.15 842.35,-1896.15 4847.35,-1896.15 4847.35,-1286.15
  text "COMPONENTS MARKED 'DNP' SHOULD NOT BE POPULATED." at 4639.85,-1080.15 h25
  text ".VariantName" at 3595.85,-1196.15 h25
  text "ASSEMBLY VARIANT:" at 4634.85,-1196.15 h25
  text "SVN REV:" at 79.35,-1418.32 h25
  text ".PCB_Rev" at 625.85,-1418.32 h25
  text "REV:" at 917.35,-1418.32 h25
  text ".PRJ_Number" at 1761.85,-1418.32 h25
  text "BOARD #:" at 2307.35,-1418.32 h25
  text "PCB VIEWED FROM BOTTOM SIDE" at 4783.85,-1418.32 h25
  text ".TIDA" at 1908,-1601 h25
  text "LAYER NAME =" at 4778.85,-1603.15 h25
  text "TID #:" at 2314.15,-1607.82 h25
  text ".Layer_Name" at 4005.85,-1610.15 h25
  text ".Print_Time" at 706.85,-1826.99 h25
  text ".Print_Date" at 1435.85,-1826.99 h25
  text "GENERATED    :" at 2305.35,-1826.99 h25
  text ".plot_File_Name" at 3978.35,-1826.99 h25
  text "PLOT NAME =" at 4783.85,-1826.99 h25
M9 Title Sheet:
  drawing of 57 lines, arcs and shapes, not listed
  text "1" at -722.31,7274.35 h70
  text "2" at 1773.35,7274.35 h70
  text "3" at 4262.69,7274.35 h70
  text "4" at 6769.36,7274.35 h70
  text "5" at 9268.35,7274.35 h70
  text "6" at 11773.35,7274.35 h70
  text "A" at -1878.65,6131.35 h70
  text "A" at 12921.35,6131.35 h70
  text "B" at -1878.65,3751.35 h70
  text "B" at 12921.35,3751.35 h70
  text "C" at -1878.65,1376.35 h70
  text "C" at 12921.35,1376.35 h70
  text "PROJECT TITLE:" at 9881.35,-484.65 h45
  text ".PRJ_Title" at 10033.85,-619.15 h50
  text "DESIGNED FOR:" at 9881.35,-785.65 h45
  text ".PRJ_Customer" at 9931.35,-925.65 h70
  text "D" at -1878.65,-993.65 h70
  text "D" at 12921.35,-993.65 h70
  text "FILE NAME:" at 9881.35,-1085.65 h45
  text ".PCB_File_Name_No_Path" at 9931.35,-1205.65 h70
  text "Texas Instruments (TI) and/or its licensors do not warrant the accuracy or completeness of this specification" at 4911.85,-1367.49 h45
  text "ENGINEER:" at 9881.35,-1375.65 h45
  text "LAYOUT BY:" at 11386.35,-1375.65 h45
  text "or any information contained therein. TI and/or its licensors do not warrant that this design will meet" at 4866.86,-1480.15 h45
  text ".PRJ_Engineer" at 9931.35,-1530.64 h70
  text ".PCB_Layout" at 11436.85,-1530.64 h70
  text "the specifications, will be suitable for your application or fit for any particular purpose, or will operate in" at 4866.86,-1592.82 h45
  text "ALTIUM DESIGNER VERSION:" at 11386.35,-1685.65 h45
  text "an implementation. TI and/or its licensors do not warrant that the design is production worthy. You should" at 4866.86,-1705.48 h45
  text "completely validate and test your design implementation to confirm the system functionality for your application." at 4911.85,-1818.15 h45
  text ".print_Scale" at 9931.35,-1818.98 h70
  text ".Application_BuildNumber" at 11436.85,-1818.98 h70
  text "2" at 1773.35,-2025.65 h70
  text "3" at 4262.69,-2025.65 h70
  text "4" at 6769.36,-2025.65 h70
  text "5" at 9268.35,-2025.65 h70
  text "6" at 11773.35,-2025.65 h70
M10 Fab Notes:
  drawing of 228 lines, arcs and shapes, not listed
  text "DESIGN INFORMATION" at 10918.87,6047.85 h60
  text "(REFER ALSO ARRAY/PANEL PROFILING INFORMATION)" at 10557.31,5886.14 h60
  text "BOARD SIZE" at 9871.31,5881.85 h60
  text "65mm" at 10333.63,5754.03 h60
  text "X" at 10839.31,5754.03 h60
  text "60mm" at 11070.63,5754.03 h60
  text "Number of Layers :" at 10274.31,5556.85 h60
  text "4" at 11369.12,5546.85 h60
  text "MIN. TRACK WIDTH:" at 10274.31,5417.85 h60
  text "8" at 11370.55,5417.85 h60
  text "MIL" at 11525.31,5417.85 h60
  text "MIN. CLEARANCE:" at 10274.31,5285.85 h60
  text "MIL" at 11525.31,5285.85 h60
  text "7.7" at 11330.85,5282.85 h60
  text "MIN. VIA DRILL SIZE:" at 10274.31,5153.85 h60
  text "MIL" at 11525.31,5153.85 h60
  text "7.87" at 11270.85,5150.85 h60
  text "5.91 MIL" at 10969.31,5012.14 h60
  text "MINIMUM ANNULAR RING" at 9945.08,5007.86 h60
  text "EXTERNAL" at 11677.31,5007.86 h60
  text "PER" at 10145.08,4889.85 h60
  text "IPC-D-275 CLASS 2 LEVEL C" at 10365.08,4889.85 h60
  text "MIL, HOLES" at 11853.31,4777.56 h60
  text "+/-" at 11460.85,4776.85 h60
  text "+/-" at 12314.85,4776.85 h60
  text "REGISTRATION TOLERANCES:" at 9945.08,4771.85 h60
  text "METAL" at 11144.85,4771.85 h60
  text "5" at 11721.05,4771.85 h60
  text "3" at 12554.05,4771.85 h60
  text "MIL" at 12670.31,4771.85 h60
  text "MATERIAL:" at 9870.31,4562.39 h60
  text "FR-4 High Tg" at 10856.75,4422.06 h60
  text "X" at 10696.85,4414.85 h60
  text "FR-408" at 10291.31,4413.49 h60
  text "OTHER" at 11779.31,4413.49 h60
  text "63 MIL (1.6mm) +/-10%" at 10611.41,4250.77 h60
  text "THICKNESS:" at 9945.08,4246.49 h60
  text "X" at 10483.25,4246.49 h60
  text "OTHER" at 11896.31,4246.49 h60
  text "TOLERANCE:" at 9945.08,4088.49 h60
  text "X" at 10784.38,4088.49 h60
  text "ANSI IPC-6012 TYPE 3 CLASS 2" at 10971.33,4088.49 h60
  text "OTHER +/-" at 10971.31,3932.49 h60
  text "BOW & TWIST:" at 9945.08,3775.49 h60
  text "X" at 10784.38,3775.49 h60
  text "ANSI IPC-6012 TYPE 3 CLASS 2" at 10971.33,3775.49 h60
  text "OTHER +/-" at 10971.31,3616.98 h60
  text "COPPER THICKNESS (FINISHED):" at 9870.31,3481.49 h60
  text "1.4MIL (1oz)" at 10750.31,3328.77 h60
  text "2MIL (1.4oz)" at 11517.31,3328.77 h60
  text "2.8MIL (2oz)" at 12244.31,3328.77 h60
  text "X" at 12111.85,3326.85 h60
  text "OUTER:" at 10227.31,3324.49 h60
  text "1.4MIL (1oz)" at 10750.31,3171.77 h60
  text "2.8MIL (2oz)" at 11517.31,3171.77 h60
  text "N/A" at 12243.85,3172.14 h60
  text "X" at 11400.85,3168.85 h60
  text "INNER SIGNAL:" at 9938.23,3167.49 h60
  text "DRILLING:" at 9870.31,3028.49 h60
  text "REFERENCE:" at 9945.08,2911.49 h60
  text "X" at 10593.31,2911.49 h60
  text "AS SHOWN" at 10780.31,2911.49 h60
  text "X" at 11494.31,2911.49 h60
  text "NC_DRILL FILES" at 11631.31,2911.49 h60
  text "PTH MIN COPPER THICKNESS:" at 9945.08,2753.49 h60
  text "X" at 11295.31,2753.49 h60
  text "1MIL" at 11432.31,2753.49 h60
  text "OTHER" at 11929.31,2753.49 h60
  text "BOARD FINISH:" at 9870.31,2594.49 h60
  text "SILKSCREEN:" at 10025.53,2476.49 h60
  text "X" at 10974.31,2476.49 h60
  text "TOP" at 11100.31,2476.49 h60
  text "X" at 11484.31,2476.49 h60
  text "BOTTOM" at 11611.31,2476.49 h60
  text "SILKSCREEN COLOR:" at 10025.53,2309.49 h60
  text "X" at 10973.27,2309.49 h60
  text "WHITE" at 11100.31,2309.49 h60
  text "OTHER" at 11611.31,2309.49 h60
  text "SOLDER RESIST COLOR:" at 10025.53,2139.49 h60
  text "X" at 10593.27,1980.29 h60
  text "GREEN" at 10720.31,1980.29 h60
  text "BLUE" at 11311.31,1980.29 h60
  text "OTHER" at 11849.31,1980.29 h60
  text "IMMERSION GOLD (ENIG)" at 10931.31,1791.77 h60
  text "ENEPIG" at 12268.85,1788.49 h60
  text "SURFACE FINISH:" at 9870.31,1787.49 h60
  text "X" at 10744.36,1787.49 h60
  text "IMM. TIN/SILVER OR EQUIV" at 10199.85,1630.49 h60
  text "OTHER" at 11631.31,1630.49 h60
  text "ARRAY/PANEL:" at 9870.31,1451.49 h60
  text "CUT AND TRIM PER MECH LAYER 1" at 10931.31,1447.2 h60
  text "N.C. ROUTE" at 10931.31,1295.49 h60
  text "X" at 11610.31,1295.49 h60
  text "V. SCORE" at 11797.31,1295.49 h60
  text "CERTIFICATION:" at 9870.31,1158.49 h60
  text "MATERIALS AND WORKMANSHIP FOR ALL PCBS" at 10595.31,1158.49 h60
  text "TO MEET OR EXCEED THE REQUIREMENTS OF:" at 10595.31,1060.49 h60
  text "X" at 10221.81,923.99 h60
  text "ANSI IPC-A-600F CLASS ->" at 10360.81,923.99 h60
  text "X" at 11999.87,923.99 h60
  text "2" at 12118.81,923.99 h60
  text "1" at 11803.81,922.49 h60
  text "3" at 12472.81,922.49 h60
  text "NOTE :" at 2935,917 h60
  text "Only 12 mil vias are tented , others are not tented." at 3197,815 h60
  text "X" at 10223.87,764.49 h60
  text "UL 94V-0" at 10360.81,764.49 h60
  text "X" at 11035.87,764.49 h60
  text "RoHS" at 11172.81,764.49 h60
  text "OTHER" at 11817.21,764.49 h60
  text "PER ORDER" at 12214.27,764.49 h60
  text "VIA TENTING:" at 11087.85,630.85 h60
  text "ADDITIONAL REQUIREMENTS:" at 9870.31,623.49 h60
  text "YES" at 11637.52,621.77 h60
  text "NO" at 12002.32,616.54 h60
  text "MICROSECTION:" at 9945.08,508.49 h60
  text "YES" at 10850.81,508.49 h60
  text "IMPEDANCE CONTROL:" at 11109.85,501.85 h60
  text "YES" at 12093.85,500.85 h60
  text "X" at 12635.85,493.85 h60
  text "NO" at 12469.32,483.54 h60
  text "REQUIRED" at 11712.31,352.35 h60
  text "BARE BOARD ELEC. TEST:" at 9945.08,349.49 h60
  text "NONE" at 11250.81,349.49 h60
  text "X" at 11585.31,349.49 h60
  text "PER ORDER" at 12304.31,349.49 h60
  text "MANUFACTURER'S UL:" at 9945.08,192.49 h60
  text "RAIL" at 11110.81,188.2 h60
  text "METAL" at 11602.62,188.2 h60
  text "X" at 11977.85,187.85 h60
  text "SILK" at 12114.31,188.2 h60
M11 Gerber Information:
  lines w10: -1754.15,-1692.32 4845.85,-1692.32 ; -1754.15,-1488.98 4847.85,-1488.98 ; -1754.15,-1285.65 -1754.15,-1895.65 2250.85,-1895.65 4847.85,-1895.65 4847.85,-1285.65 -1753.65,-1285.65 -1753.65,-1895.65 ; 710.85,-1895.65 710.85,-1285.65 ; 1977.85,-1488.98 1977.85,-1285.65 ; 2817.85,-1488.98 2817.85,-1285.65 ; 3439.85,-1902.15 3439.85,-1699.32
  text "BOARD #:" at 785.85,-1417.82 h60
  text ".PRJ_Number" at 1331.35,-1417.82 h60
  text "REV:" at 2175.85,-1417.82 h60
  text ".PCB_Rev" at 2467.35,-1417.82 h60
  text "SVN REV:" at 3013.85,-1417.82 h60
  text ".VersionControl_RevNumber" at 3519.85,-1417.82 h60
  text "ALL ARTWORK VIEWED FROM TOP SIDE" at -1691.65,-1423.82 h60
  text "LAYER NAME =" at -1693.15,-1607.15 h60
  text ".TID" at 1181,-1615 h60
  text "TID #:" at 774.85,-1621.82 h60
  text ".plot_File_Name" at -1701.15,-1806.15 h60
  text "GENERATED    :" at 787.85,-1826.49 h60
  text ".Print_Date" at 1657.35,-1826.49 h60
  text ".Print_Time" at 2386.35,-1826.49 h60
  text "TEXAS INSTRUMENTS" at 3650.85,-1826.49 h60
M12 Stackup:
  lines w6: 9897.85,6697.85 12447.85,6697.85 ; 9897.85,6802.25 12447.85,6802.25 ; 9837.85,6212.85 ccw(c9871.85,6212.85) 9871.85,6178.85 12473.85,6178.85 ccw(c12473.85,6212.85) 12507.85,6212.85 12507.85,6918.85 ccw(c12473.85,6918.85) 12473.85,6952.85 9871.85,6952.85 ccw(c9871.85,6918.85) 9837.85,6918.85 9837.85,6212.85
  text "Layer Stack Up Detail for: TIDA-00774_E2" at 9897.85,6834.95 h57
  text "Layer" at 9897.85,6763.25 h24
  text "Gerber" at 10793.66,6763.25 h24
  text "Copper" at 11357.18,6763.25 h24
  text "Dielectric" at 11959.89,6763.25 h24
  text "Name" at 9897.85,6715.25 h24
  text "Document" at 10793.66,6715.25 h24
  text "Thickness" at 11357.18,6715.25 h24
  text "Material" at 11959.89,6715.25 h24
  text "Top Solder Mask" at 9897.85,6622.29 h34
  text "(.GTS)" at 10793.66,6622.29 h34
  text "Solder Resist" at 11959.89,6622.29 h34
  text "Top Layer" at 9897.85,6525.54 h34
  text "(.GTL)" at 10793.66,6525.54 h34
  text "2.8mil" at 11357.18,6525.54 h34
  text "FR-4 High Tg" at 11988.85,6524.85 h34
  text "(.G1)" at 10793.66,6453.54 h34
  text "2.8mil" at 11359.18,6453.54 h34
  text "FR-4 High Tg" at 11989.85,6453.85 h34
  text "GND" at 9904.85,6451.85 h34
  text "(.G2)" at 10792.66,6381.54 h34
  text "FR-4 High Tg" at 11989.85,6379.85 h34
  text "2.8mil" at 11359.18,6370.54 h34
  text "PWR" at 9906.85,6366.85 h34
  text "FR-4 High Tg" at 11990.85,6305.85 h34
  text "Bottom Layer" at 9903.85,6295.85 h34
  text "(.GBL)" at 10801.85,6294.85 h34
  text "2.8mil" at 11361.85,6288.85 h34
  text "Solder Resist" at 11953.85,6221.85 h34
  text "(.GBS)" at 10798.85,6214.85 h34
  text "Bottom Solder Mask" at 9900.85,6209.85 h34
M13 Component Bodies Top:
  text ".Layer_Name" at -885.15,-1620.64 h60
M14 Component Bodies Bottom:
  text ".Layer_Name" at -885.15,-1620.64 h60
M15 Courtyards Top:
  text ".Layer_Name" at -885.15,-1620.64 h60
M16 Courtyards Bottom:
  text ".Layer_Name" at -885.15,-1620.64 h60
Drill Drawing:
  text ".legend" at 3205.23,1534.31 h60
  text "Drill Table" at 3205.23,1441.31 h60
  text "FOR 7.874MIL DRILL +0/-7.874MIL" at 3198.23,1270.31 h60
  text "FOR 12MIL DRILL +0/-12MIL" at 3196.23,1170.31 h60
  text "FOR PTH DRILL +/-3MIL" at 3198,1089 h60
  text "FOR NPTH DRILL +/-2MIL" at 3197,996 h60
  text ".layer_Name" at -780.15,-1604.15 h60

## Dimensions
0,2362.2 to 0,0 on M2 Board Dimensions
0,0 to 2559.06,0 on M2 Board Dimensions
